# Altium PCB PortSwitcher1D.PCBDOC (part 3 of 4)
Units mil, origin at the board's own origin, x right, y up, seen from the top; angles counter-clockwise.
Board outline 6005.03 x 6005.03 mil, 4 copper layers (Top Layer, InternalPlane1, InternalPlane2, Bottom Layer); 153 components, 325 nets, 1175 pads, 173 vias.
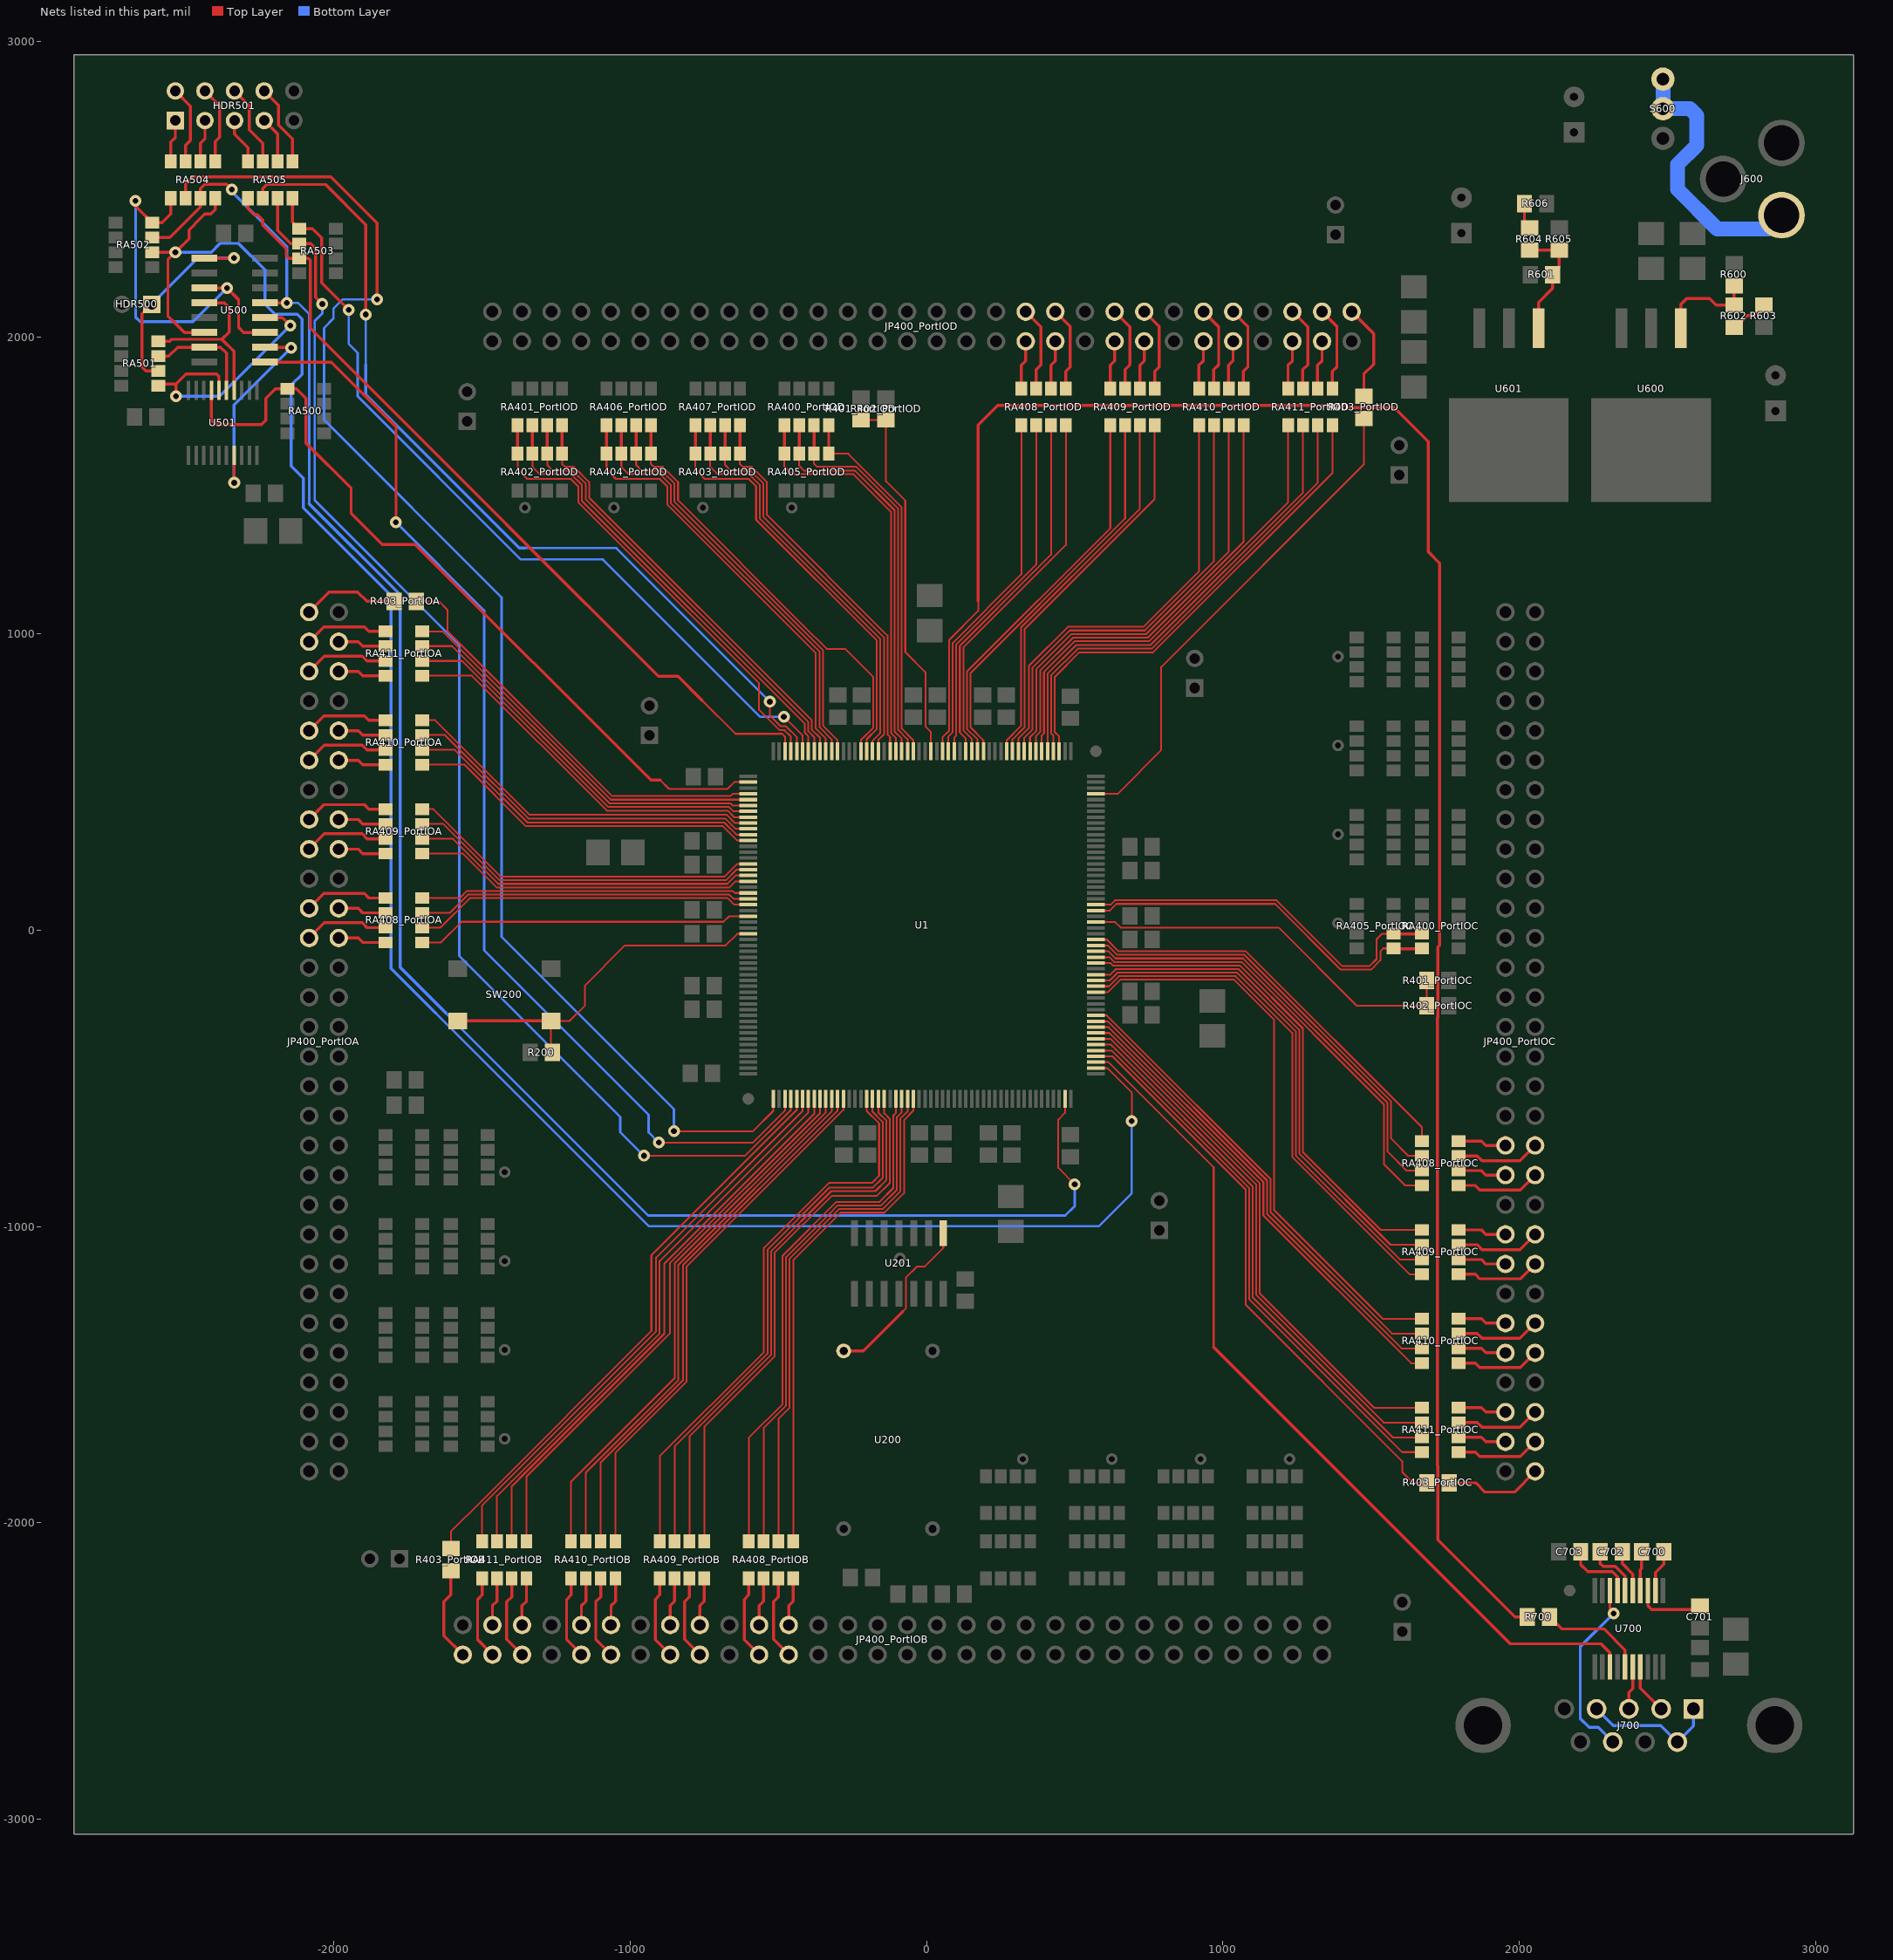
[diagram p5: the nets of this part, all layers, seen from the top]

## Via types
v1: diameter 40, hole 19.68, Top Layer to Bottom Layer, 173 vias

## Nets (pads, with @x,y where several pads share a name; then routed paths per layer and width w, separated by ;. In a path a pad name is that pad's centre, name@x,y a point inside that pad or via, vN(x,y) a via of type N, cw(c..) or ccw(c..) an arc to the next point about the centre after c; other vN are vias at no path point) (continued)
INC14: RA400_PortIOC.7 RA405_PortIOC.6 U1.30 | length 1281.8
  Top Layer w6: U1.30@571.35,86.19 621.14,86.19 635.71,100.77 1180.55,100.77 1401.82,-120.5 1495.13,-120.5 1518.2,-97.43 1518.2,-30.74 1537.53,-11.41 RA405_PortIOC.6@1575.24,-11.41
  Top Layer w10: RA405_PortIOC.6@1574.1,-12.55 RA400_PortIOC.7@1670.1,-12.55
INC15: RA400_PortIOC.8 RA405_PortIOC.5 U1.29 | length 1248.7
  Top Layer w6: U1.29@571.35,66.5 618.42,66.51 640.68,88.77 1175.58,88.77 1397.65,-133.3 1499.3,-133.3 1531,-101.61 1531,-71.09 1540.68,-61.41 RA405_PortIOC.5@1575.24,-61.41
  Top Layer w10: RA405_PortIOC.5@1574.1,-62.55 RA400_PortIOC.8@1670.1,-62.55
INC16: R401_PortIOC.2 R402_PortIOC.1 U1.27 | length 1582.4
  Top Layer w6: U1.27@571.35,27.13 636.49,27.14 654.86,8.77 1187.78,8.77 ; 1374.65,-178.1 1187.78,8.77 ; R401_PortIOC.2@1687.6,-170 R402_PortIOC.1@1687.6,-255 1451.54,-255 1187.78,8.77
IND0: RA401_PortIOD.5 RA402_PortIOD.8 U1.101 | length 1578.3
  Top Layer w6: RA402_PortIOD.8@-1380.26,1607.8 -1380.26,1554.93 -1348.53,1523.2 -1200.63,1523.2 -1175.49,1498.06 -1175.49,1444.01 -565.46,833.98 -565.46,743.67 -496.56,674.77 -479.83,674.77 -458.18,653.12 U1.101@-458.18,603.91
  Top Layer w10: RA402_PortIOD.8@-1380.26,1607.8 RA401_PortIOD.5@-1380.26,1703.8
IND1: RA401_PortIOD.6 RA402_PortIOD.7 U1.98 | length 1547.7
  Top Layer w6: RA402_PortIOD.7@-1330.26,1607.8 -1330.26,1563.99 -1305.04,1538.76 -1199.21,1538.76 -1163.49,1503.04 -1163.49,1448.98 -411.11,696.6 -411.11,666.32 ; -411.11,666.42 -399.12,654.43 U1.98@-399.12,603.91
  Top Layer w10: RA402_PortIOD.7@-1330.26,1607.8 RA401_PortIOD.6@-1330.26,1703.8
IND2: RA401_PortIOD.7 RA402_PortIOD.6 U1.97 | length 1512.1
  Top Layer w6: RA402_PortIOD.6@-1280.26,1607.8 -1280.26,1570.09 -1260.93,1550.76 -1194.24,1550.76 -1150.89,1507.4 -1150.89,1454.09 -399.11,702.32 -399.11,671.42 -379.44,651.75 U1.97@-379.44,603.91
  Top Layer w10: RA402_PortIOD.6@-1280.26,1607.8 RA401_PortIOD.7@-1280.26,1703.8
IND3: RA401_PortIOD.8 RA402_PortIOD.5 U1.96 | length 1478.4
  Top Layer w6: RA402_PortIOD.5@-1230.26,1607.8 -1230.26,1573.24 -1220.58,1563.55 -1190.07,1563.55 -1138.89,1512.37 -1138.89,1459.81 -387.11,708.03 -387.11,676.39 -359.75,649.03 U1.96@-359.75,603.91
  Top Layer w10: RA402_PortIOD.5@-1230.26,1607.8 RA401_PortIOD.8@-1230.26,1703.8
IND4: RA404_PortIOD.8 RA406_PortIOD.5 U1.95 | length 1493.1
  Top Layer w6: RA404_PortIOD.8@-1080.26,1607.8 -1080.26,1554.93 -1048.53,1523.2 -900.63,1523.2 -875.49,1498.06 -875.49,1436.84 -375.11,936.46 -375.11,681.42 -340.07,646.38 U1.95@-340.07,603.91
  Top Layer w10: RA404_PortIOD.8@-1080.26,1607.8 RA406_PortIOD.5@-1080.26,1703.8
IND5: RA404_PortIOD.7 RA406_PortIOD.6 U1.94 | length 1455.9
  Top Layer w6: RA404_PortIOD.7@-1030.26,1607.8 -1030.26,1563.99 -1005.04,1538.76 -899.21,1538.76 -863.49,1503.04 -863.49,1441.82 -361.11,939.43 -361.11,684.42 -320.38,643.69 U1.94@-320.38,603.91
  Top Layer w10: RA404_PortIOD.7@-1030.26,1607.8 RA406_PortIOD.6@-1030.26,1703.8
IND6: RA404_PortIOD.6 RA406_PortIOD.7 U1.93 | length 1420.4
  Top Layer w6: RA404_PortIOD.6@-980.26,1607.8 -980.26,1570.09 -960.93,1550.76 -894.24,1550.76 -850.89,1507.4 -850.89,1446.18 -349.11,944.4 -349.11,689.42 -300.7,641.01 U1.93@-300.7,603.91
  Top Layer w10: RA404_PortIOD.6@-980.26,1607.8 RA406_PortIOD.7@-980.26,1703.8
IND7: RA404_PortIOD.5 RA406_PortIOD.8 U1.89 | length 1482.2
  Top Layer w6: RA404_PortIOD.5@-930.26,1607.8 -930.26,1573.24 -920.58,1563.55 -890.07,1563.55 -838.89,1512.37 -838.89,1451.15 -414.55,1026.82 -337.36,949.62 -275.31,949.62 -180.11,854.42 -180.11,683.4 -221.96,641.55 U1.89@-221.96,603.91
  Top Layer w10: RA404_PortIOD.5@-930.26,1607.8 RA406_PortIOD.8@-930.26,1703.8
IND8: RA403_PortIOD.8 RA407_PortIOD.5 U1.88 | length 1454.2
  Top Layer w6: RA403_PortIOD.8@-780.26,1607.8 -780.26,1554.93 -748.53,1523.2 -600.63,1523.2 -575.49,1498.06 -575.49,1384.61 -168.11,977.22 -168.11,678.43 -202.27,644.26 U1.88@-202.27,603.91
  Top Layer w10: RA403_PortIOD.8@-780.26,1607.8 RA407_PortIOD.5@-780.26,1703.8
IND9: RA403_PortIOD.7 RA407_PortIOD.6 U1.87 | length 1410.7
  Top Layer w6: RA403_PortIOD.7@-730.26,1607.8 -730.26,1563.99 -705.04,1538.76 -599.21,1538.76 -563.49,1503.04 -563.49,1390.09 -156.11,982.7 -156.11,665.51 -182.59,639.03 U1.87@-182.59,603.91
  Top Layer w10: RA403_PortIOD.7@-730.26,1607.8 RA407_PortIOD.6@-730.26,1703.8
IND10: RA403_PortIOD.6 RA407_PortIOD.7 U1.86 | length 1368.8
  Top Layer w6: RA403_PortIOD.6@-680.26,1607.8 -680.26,1570.09 -660.93,1550.76 -594.24,1550.76 -550.89,1507.4 -550.89,1394.45 -144.11,987.67 -144.11,660.54 -162.9,641.74 U1.86@-162.9,603.91
  Top Layer w10: RA403_PortIOD.6@-680.26,1607.8 RA407_PortIOD.7@-680.26,1703.8
IND11: RA403_PortIOD.5 RA407_PortIOD.8 U1.84 | length 1327.7
  Top Layer w6: RA403_PortIOD.5@-630.26,1607.8 -630.26,1573.24 -620.58,1563.55 -590.07,1563.55 -538.89,1512.37 -538.89,1401.15 -132.11,994.37 -132.11,660.54 -123.53,651.96 U1.84@-123.53,603.91
  Top Layer w10: RA403_PortIOD.5@-630.26,1607.8 RA407_PortIOD.8@-630.26,1703.8
IND12: RA400_PortIOD.5 RA405_PortIOD.8 U1.83 | length 1377.2
  Top Layer w6: RA405_PortIOD.8@-480.26,1607.8 -480.26,1564.97 -454.05,1538.76 -246.85,1538.76 -120.11,1412.01 -120.11,665.51 -103.85,649.25 U1.83@-103.85,603.91
  Top Layer w10: RA405_PortIOD.8@-480.26,1607.8 RA400_PortIOD.5@-480.26,1703.8
IND13: RA400_PortIOD.6 RA405_PortIOD.7 U1.82 | length 1344
  Top Layer w6: RA405_PortIOD.7@-430.26,1607.8 -430.26,1567.13 -413.89,1550.76 -241.88,1550.76 -108.11,1416.98 -108.11,670.48 -84.16,646.53 U1.82@-84.16,603.91
  Top Layer w10: RA405_PortIOD.7@-430.26,1607.8 RA400_PortIOD.6@-430.26,1703.8
IND14: RA400_PortIOD.7 RA405_PortIOD.6 U1.81 | length 1308
  Top Layer w6: RA405_PortIOD.6@-380.26,1607.8 -380.26,1574.22 -370.58,1564.54 -238.69,1564.54 -96.11,1421.95 -96.11,675.45 -64.48,643.82 U1.81@-64.48,603.91
  Top Layer w10: RA405_PortIOD.6@-380.26,1607.8 RA400_PortIOD.7@-380.26,1703.8
IND15: RA400_PortIOD.8 RA405_PortIOD.5 U1.80 | length 1256.6
  Top Layer w6: RA405_PortIOD.5@-330.26,1607.8 -264.64,1607.8 -84.11,1427.27 -84.11,680.42 -44.79,641.1 U1.80@-44.79,603.91
  Top Layer w10: RA405_PortIOD.5@-330.26,1607.8 RA400_PortIOD.8@-330.26,1703.8
IND16: R401_PortIOD.2 R402_PortIOD.1 U1.77 | length 1265.5
  Top Layer w6: R401_PortIOD.2@-222.07,1721.73 R402_PortIOD.1@-137.07,1721.73 -137.07,1514.67 -72.11,1449.71 -72.11,938.67 -4.11,870.67 -4.11,687.42 14.26,669.05 U1.77@14.26,603.91
JTAG_NEXUS_TCK: RA503.2 RA505.3 U1.160 | length 4401.5
  Top Layer w6: v1(-954,-761.05) -612.55,-761.05 -458.18,-606.68 U1.160@-458.18,-569.32
  Top Layer w10: RA505.3@-2190.26,2470.29 -2190.26,2361.54 -2146.02,2317.29 -2078.12,2317.29 -2061.98,2301.16 -2061.98,2135.84 v1(-2039.35,2113.21)
  Bottom Layer w8: v1(-2039.35,2113.21) -2039.35,2081.72 -2064.94,2056.14 -2064.94,1450.98 -1576.87,962.92 -1576.87,-87.01 -1033.7,-630.18 -1033.7,-681.35 v1(-954,-761.05)
JTAG_NEXUS_TDI: RA503.3 RA505.1 U1.102 | length 2793.5
  Top Layer w6: -757.2,774.97 -645,662.77 -568.25,662.77 -487.52,662.77 -477.86,653.12 U1.102@-477.86,603.91
  Top Layer w10: RA505.1@-2290.26,2470.29 -2290.26,2434.91 -2269.1,2413.75 -2257.3,2413.75 -2240.26,2396.72 -2240.26,2379.07 -2161.28,2300.08 -2161.28,2276.47 -2152.1,2267.29 -2086.18,2267.29 -2079.7,2260.81 -2079.7,2031.54 -1450.79,1402.63 -1385.85,1337.7 -904.8,856.64 -838.87,856.64 -757.2,774.97
JTAG_NEXUS_TDO: RA505.2 U1.100 | length 3023.3
  Top Layer w6: v1(-529.04,771.23) -529.04,724.97 -492.63,688.55 -474.91,688.55 -438.49,652.13 U1.100@-438.49,603.91
  Top Layer w10: RA505.2@-2240.26,2470.29 -2240.26,2503.18 -2226.79,2516.65 -2028.53,2516.65 -1892.74,2380.86 v1(-1892.74,2077.79)
  Bottom Layer w8: -1892.74,1907.56 v1(-1892.74,2077.79) ; -1355.47,1289.6 -1047.42,1289.6 v1(-529.04,771.23)
  Bottom Layer w10: -1892.74,1907.56 -1892.74,1808.17 -1374.17,1289.6 -1355.47,1289.6
JTAG_NEXUS_TMS: RA503.1 RA505.4 U1.99 | length 2814.2
  Top Layer w6: v1(-481.8,720.05) -419.77,658.02 -419.77,657.12 ; U1.99@-418.81,603.91 -418.81,657.12
  Top Layer w10: RA505.4@-2140.26,2470.29 -2140.26,2390.29 RA503.1@-2117.26,2367.29 -2072.03,2367.29 -2041.32,2336.58 -2041.32,2185.04 v1(-1949.81,2093.53)
  Bottom Layer w8: v1(-1949.81,2093.53) -1949.81,1978.4 -1919.98,1948.58 -1919.98,1801.96 -1369.25,1251.23 -1092.74,1251.23 -561.56,720.05 v1(-481.8,720.05)
NetC700_1: C700.1 U700.2 | length 142.6
  Top Layer w10: U700.2@2459.3,-2228.77 2459.3,-2167.38 2487.14,-2139.55 C700.1@2487.14,-2097.71
NetC700_2: C700.2 U700.4 | length 132.8
  Top Layer w10: U700.4@2408.12,-2228.77 2408.12,-2158.54 2412.33,-2154.33 C700.2@2412.33,-2097.71
NetC701_2: C701.2 U700.3 | length 236.7
  Top Layer w10: U700.3@2433.71,-2228.77 2433.71,-2279.16 2446.7,-2292.16 2597.89,-2292.16 C701.2@2609.74,-2280.31
NetC702_1: C702.1 U700.5 | length 145.7
  Top Layer w10: C702.1@2347.14,-2097.71 2347.14,-2137.49 2382.53,-2172.88 U700.5@2382.53,-2228.77
NetC702_2: C702.2 U700.6 | length 190.9
  Top Layer w10: C702.2@2272.33,-2097.71 2272.33,-2137.47 2282.38,-2147.51 2324.69,-2147.51 2356.94,-2179.76 U700.6@2356.94,-2228.77
NetC703_1: C703.1 U700.7 | length 230.9
  Top Layer w10: C703.1@2207.14,-2097.71 2207.14,-2141.15 2231.21,-2165.22 2313.86,-2165.22 2331.35,-2182.71 U700.7@2331.35,-2228.77
NetHDR500_1: HDR500.1 RA501.2 U500.1 | length 727.9
  Top Layer w10: HDR500.1@-2615.26,2112.29 -2647.46,2080.09 -2647.46,1900.67 -2634.09,1887.29 RA501.2@-2593.26,1887.29 ; U500.1@-2437.63,2267.29 -2338.9,2267.29 v1(-2337.5,2268.68)
  Bottom Layer w10: HDR500.1@-2615.26,2112.29 -2458.87,2268.68 v1(-2337.5,2268.68)
NetJ700_1: J700.1 J700.4 J700.6 | length 453.3
  Bottom Layer w10: J700.4@2260.68,-2627.79 2316.68,-2683.79 2477.51,-2683.79 J700.6@2533.32,-2739.6 2587.85,-2685.07 J700.1@2587.85,-2627.79
NetR600_1: R600.1 R602.2 U600.1 | length 342.3
  Top Layer w10: U600.1@2544.74,2032.29 2544.74,2111.86 2564.78,2131.91 2641.54,2131.91 2663.75,2109.69 R602.2@2724.74,2109.69 R600.1@2724.74,2174.89
NetR601_1: R601.1 R604.2 R605.2 U601.1 | length 391.6
  Top Layer w10: R604.2@2034.74,2294.89 R605.2@2134.74,2294.89 2134.74,2234.89 R601.1@2112.14,2212.29 2112.14,2166.34 2064.74,2118.94 U601.1@2064.74,2032.29
NetR602_1: R602.1 R603.2 | length 131
  Top Layer w10: R602.1@2724.74,2034.89 2729.51,2034.89 2769.46,2074.84 2789.88,2074.84 R603.2@2824.74,2109.69
NetR604_1: R604.1 R606.2 | length 89.8
  Top Layer w10: R606.2@2017.33,2452.29 2017.33,2387.1 R604.1@2034.74,2369.69
NetR700_1: R700.1 U700.15 | length 358.4
  Top Layer w10: R700.1@2102.14,-2317.71 2142.51,-2358.08 2285.83,-2358.08 2356.94,-2429.19 U700.15@2356.94,-2486.65
NetRA501_1: RA501.1 U500.12 U501.6 | length 893.6
  Top Layer w10: RA501.1@-2593.26,1837.29 -2587.76,1842.79 -2533.32,1842.79 ; v1(-2533.32,1802.27) -2533.32,1842.79 ; U501.6@-2388.06,1821.54 -2388.06,1868.57 -2396.54,1877.05 -2499.06,1877.05 -2533.32,1842.79 ; U500.12@-2232.9,2067.29 -2174.49,2067.29 v1(-2147.59,2040.4)
  Bottom Layer w10: v1(-2533.32,1802.27) -2385.72,1802.27 v1(-2147.59,2040.4)
NetRA501_3: RA501.3 U500.7 U501.5 | length 377.2
  Top Layer w10: RA501.3@-2593.26,1937.29 -2557.7,1937.29 -2527.7,1967.29 -2382.48,1967.29 -2362.47,1947.28 U501.5@-2362.47,1821.54
NetRA501_4: RA501.4 U500.4 U501.4 | length 615.7
  Top Layer w10: RA501.4@-2593.26,1987.29 -2553.98,1987.29 -2547.13,1994.15 -2377.85,1994.15 ; U500.4@-2437.63,2117.29 -2370.12,2117.29 -2353.25,2100.42 -2353.25,2018.75 -2377.85,1994.15 ; U501.4@-2336.88,1821.54 -2336.88,1953.18 -2377.85,1994.15
NetU200_8: U200.8 U201.1 | length 591.3
  Top Layer w6: -81.1,-1287.72 -70.38,-1277 -70.38,-1172.67 -32.98,-1135.27 -7,-1135.27 56,-1072.28 U201.1@56,-1022.08
  Top Layer w10: U200.8@-280,-1420 -213.38,-1420 -81.1,-1287.72
O0_PortIOA: JP400_PortIOA.38 RA408_PortIOA.4 | length 164.2
  Top Layer w10: JP400_PortIOA.38@-1983.77,-26.41 -1918.02,-26.41 -1903.02,-41.41 RA408_PortIOA.4@-1825.77,-41.41
O0_PortIOB: JP400_PortIOB.38 RA408_PortIOB.4 | length 164.2
  Top Layer w10: JP400_PortIOB.38@-465.26,-2344.91 -465.26,-2279.17 -450.26,-2264.17 RA408_PortIOB.4@-450.26,-2186.91
O0_PortIOC: JP400_PortIOC.38 RA408_PortIOC.4 | length 164.2
  Top Layer w10: RA408_PortIOC.4@1795.24,-711.41 1872.49,-711.41 1887.49,-726.41 JP400_PortIOC.38@1953.24,-726.41
O0_PortIOD: JP400_PortIOD.38 RA408_PortIOD.4 | length 164.2
  Top Layer w10: RA408_PortIOD.4@319.34,1829.37 319.34,1906.62 334.34,1921.62 JP400_PortIOD.38@334.34,1987.37
O1_PortIOA: JP400_PortIOA.37 RA408_PortIOA.3 | length 286.2
  Top Layer w10: JP400_PortIOA.37@-2083.77,-26.41 -2032.19,25.17 -1905.03,25.17 -1888.45,8.59 RA408_PortIOA.3@-1825.77,8.59
O1_PortIOB: JP400_PortIOB.37 RA408_PortIOB.3 | length 286.2
  Top Layer w10: RA408_PortIOB.3@-500.26,-2186.91 -500.26,-2249.6 -516.84,-2266.17 -516.84,-2393.34 JP400_PortIOB.37@-465.26,-2444.91
O1_PortIOC: JP400_PortIOC.37 RA408_PortIOC.3 | length 286.2
  Top Layer w10: RA408_PortIOC.3@1795.24,-761.41 1857.93,-761.41 1874.5,-777.98 2001.66,-777.98 JP400_PortIOC.37@2053.24,-726.41
O1_PortIOD: JP400_PortIOD.37 RA408_PortIOD.3 | length 286.2
  Top Layer w10: JP400_PortIOD.37@334.34,2087.37 385.92,2035.8 385.92,1908.63 369.34,1892.06 RA408_PortIOD.3@369.34,1829.37
O2_PortIOA: JP400_PortIOA.40 RA408_PortIOA.2 | length 164.2
  Top Layer w10: JP400_PortIOA.40@-1983.77,73.59 -1918.02,73.59 -1903.02,58.59 RA408_PortIOA.2@-1825.77,58.59
O2_PortIOB: JP400_PortIOB.40 RA408_PortIOB.2 | length 164.2
  Top Layer w10: JP400_PortIOB.40@-565.26,-2344.91 -565.26,-2279.17 -550.26,-2264.17 RA408_PortIOB.2@-550.26,-2186.91
O2_PortIOC: JP400_PortIOC.40 RA408_PortIOC.2 | length 164.2
  Top Layer w10: RA408_PortIOC.2@1795.24,-811.41 1872.49,-811.41 1887.49,-826.41 JP400_PortIOC.40@1953.24,-826.41
O2_PortIOD: JP400_PortIOD.40 RA408_PortIOD.2 | length 164.2
  Top Layer w10: RA408_PortIOD.2@419.34,1829.37 419.34,1906.62 434.34,1921.62 JP400_PortIOD.40@434.34,1987.37
O3_PortIOA: JP400_PortIOA.39 RA408_PortIOA.1 | length 284.9
  Top Layer w10: JP400_PortIOA.39@-2083.77,73.59 -2033.77,123.59 -1897.16,123.59 -1882.16,108.59 RA408_PortIOA.1@-1825.77,108.59
O3_PortIOB: JP400_PortIOB.39 RA408_PortIOB.1 | length 284.9
  Top Layer w10: RA408_PortIOB.1@-600.26,-2186.91 -600.26,-2243.3 -615.26,-2258.3 -615.26,-2394.91 JP400_PortIOB.39@-565.26,-2444.91
O3_PortIOC: JP400_PortIOC.39 RA408_PortIOC.1 | length 284.9
  Top Layer w10: RA408_PortIOC.1@1795.24,-861.41 1851.63,-861.41 1866.63,-876.41 2003.24,-876.41 JP400_PortIOC.39@2053.24,-826.41
O3_PortIOD: JP400_PortIOD.39 RA408_PortIOD.1 | length 284.9
  Top Layer w10: JP400_PortIOD.39@434.34,2087.37 484.34,2037.37 484.34,1900.76 469.34,1885.76 RA408_PortIOD.1@469.34,1829.37
O4_PortIOA: JP400_PortIOA.44 RA409_PortIOA.4 | length 164.2
  Top Layer w10: JP400_PortIOA.44@-1983.77,273.59 -1918.02,273.59 -1903.02,258.59 RA409_PortIOA.4@-1825.77,258.59
O4_PortIOB: JP400_PortIOB.44 RA409_PortIOB.4 | length 164.2
  Top Layer w10: JP400_PortIOB.44@-765.26,-2344.91 -765.26,-2279.17 -750.26,-2264.17 RA409_PortIOB.4@-750.26,-2186.91
O4_PortIOC: JP400_PortIOC.44 RA409_PortIOC.4 | length 164.2
  Top Layer w10: RA409_PortIOC.4@1795.24,-1011.41 1872.49,-1011.41 1887.49,-1026.41 JP400_PortIOC.44@1953.24,-1026.41
O4_PortIOD: JP400_PortIOD.44 RA409_PortIOD.4 | length 164.2
  Top Layer w10: RA409_PortIOD.4@619.34,1829.37 619.34,1906.62 634.34,1921.62 JP400_PortIOD.44@634.34,1987.37
O5_PortIOA: JP400_PortIOA.43 RA409_PortIOA.3 | length 286.2
  Top Layer w10: JP400_PortIOA.43@-2083.77,273.59 -2032.19,325.17 -1905.03,325.17 -1888.45,308.59 RA409_PortIOA.3@-1825.77,308.59
O5_PortIOB: JP400_PortIOB.43 RA409_PortIOB.3 | length 286.2
  Top Layer w10: RA409_PortIOB.3@-800.26,-2186.91 -800.26,-2249.6 -816.84,-2266.17 -816.84,-2393.34 JP400_PortIOB.43@-765.26,-2444.91
O5_PortIOC: JP400_PortIOC.43 RA409_PortIOC.3 | length 286.2
  Top Layer w10: RA409_PortIOC.3@1795.24,-1061.41 1857.93,-1061.41 1874.5,-1077.98 2001.66,-1077.98 JP400_PortIOC.43@2053.24,-1026.41
O5_PortIOD: JP400_PortIOD.43 RA409_PortIOD.3 | length 286.2
  Top Layer w10: JP400_PortIOD.43@634.34,2087.37 685.92,2035.8 685.92,1908.63 669.34,1892.06 RA409_PortIOD.3@669.34,1829.37
O6_PortIOA: JP400_PortIOA.46 RA409_PortIOA.2 | length 164.2
  Top Layer w10: JP400_PortIOA.46@-1983.77,373.59 -1918.02,373.59 -1903.02,358.59 RA409_PortIOA.2@-1825.77,358.59
O6_PortIOB: JP400_PortIOB.46 RA409_PortIOB.2 | length 164.2
  Top Layer w10: JP400_PortIOB.46@-865.26,-2344.91 -865.26,-2279.17 -850.26,-2264.17 RA409_PortIOB.2@-850.26,-2186.91
O6_PortIOC: JP400_PortIOC.46 RA409_PortIOC.2 | length 164.2
  Top Layer w10: RA409_PortIOC.2@1795.24,-1111.41 1872.49,-1111.41 1887.49,-1126.41 JP400_PortIOC.46@1953.24,-1126.41
O6_PortIOD: JP400_PortIOD.46 RA409_PortIOD.2 | length 164.2
  Top Layer w10: RA409_PortIOD.2@719.34,1829.37 719.34,1906.62 734.34,1921.62 JP400_PortIOD.46@734.34,1987.37
O7_PortIOA: JP400_PortIOA.45 RA409_PortIOA.1 | length 284.9
  Top Layer w10: JP400_PortIOA.45@-2083.77,373.59 -2033.77,423.59 -1897.16,423.59 -1882.16,408.59 RA409_PortIOA.1@-1825.77,408.59
O7_PortIOB: JP400_PortIOB.45 RA409_PortIOB.1 | length 284.9
  Top Layer w10: RA409_PortIOB.1@-900.26,-2186.91 -900.26,-2243.3 -915.26,-2258.3 -915.26,-2394.91 JP400_PortIOB.45@-865.26,-2444.91
O7_PortIOC: JP400_PortIOC.45 RA409_PortIOC.1 | length 284.9
  Top Layer w10: RA409_PortIOC.1@1795.24,-1161.41 1851.63,-1161.41 1866.63,-1176.41 2003.24,-1176.41 JP400_PortIOC.45@2053.24,-1126.41
O7_PortIOD: JP400_PortIOD.45 RA409_PortIOD.1 | length 284.9
  Top Layer w10: JP400_PortIOD.45@734.34,2087.37 784.34,2037.37 784.34,1900.76 769.34,1885.76 RA409_PortIOD.1@769.34,1829.37
O8_PortIOA: JP400_PortIOA.50 RA410_PortIOA.4 | length 164.2
  Top Layer w10: JP400_PortIOA.50@-1983.77,573.2 -1918.02,573.2 -1903.02,558.2 RA410_PortIOA.4@-1825.77,558.2
O8_PortIOB: JP400_PortIOB.50 RA410_PortIOB.4 | length 164.2
  Top Layer w10: JP400_PortIOB.50@-1064.87,-2344.91 -1064.87,-2279.16 -1049.87,-2264.16 RA410_PortIOB.4@-1049.87,-2186.91
O8_PortIOC: JP400_PortIOC.50 RA410_PortIOC.4 | length 164.2
  Top Layer w10: RA410_PortIOC.4@1795.24,-1311.02 1872.49,-1311.02 1887.49,-1326.02 JP400_PortIOC.50@1953.24,-1326.02
O8_PortIOD: JP400_PortIOD.50 RA410_PortIOD.4 | length 164.2
  Top Layer w10: RA410_PortIOD.4@918.95,1829.37 918.95,1906.62 933.95,1921.62 JP400_PortIOD.50@933.95,1987.37
O9_PortIOA: JP400_PortIOA.49 RA410_PortIOA.3 | length 286.2
  Top Layer w10: JP400_PortIOA.49@-2083.77,573.2 -2032.19,624.77 -1905.03,624.77 -1888.45,608.2 RA410_PortIOA.3@-1825.77,608.2
O9_PortIOB: JP400_PortIOB.49 RA410_PortIOB.3 | length 286.2
  Top Layer w10: RA410_PortIOB.3@-1099.87,-2186.91 -1099.87,-2249.6 -1116.45,-2266.17 -1116.45,-2393.34 JP400_PortIOB.49@-1064.87,-2444.91
O9_PortIOC: JP400_PortIOC.49 RA410_PortIOC.3 | length 286.2
  Top Layer w10: RA410_PortIOC.3@1795.24,-1361.02 1857.92,-1361.02 ; 1857.92,-1361.02 1874.5,-1377.59 2001.66,-1377.59 JP400_PortIOC.49@2053.24,-1326.02
O9_PortIOD: JP400_PortIOD.49 RA410_PortIOD.3 | length 286.2
  Top Layer w10: JP400_PortIOD.49@933.95,2087.37 985.52,2035.8 985.52,1908.63 968.95,1892.06 RA410_PortIOD.3@968.95,1829.37
O10_PortIOA: JP400_PortIOA.52 RA410_PortIOA.2 | length 164.2
  Top Layer w10: JP400_PortIOA.52@-1983.77,673.2 -1918.02,673.2 -1903.02,658.2 RA410_PortIOA.2@-1825.77,658.2
O10_PortIOB: JP400_PortIOB.52 RA410_PortIOB.2 | length 164.2
  Top Layer w10: JP400_PortIOB.52@-1164.87,-2344.91 -1164.87,-2279.16 -1149.87,-2264.16 RA410_PortIOB.2@-1149.87,-2186.91
O10_PortIOC: JP400_PortIOC.52 RA410_PortIOC.2 | length 164.2
  Top Layer w10: RA410_PortIOC.2@1795.24,-1411.02 1872.49,-1411.02 1887.49,-1426.02 JP400_PortIOC.52@1953.24,-1426.02
O10_PortIOD: JP400_PortIOD.52 RA410_PortIOD.2 | length 164.2
  Top Layer w10: RA410_PortIOD.2@1018.95,1829.37 1018.95,1906.62 1033.95,1921.62 JP400_PortIOD.52@1033.95,1987.37
O11_PortIOA: JP400_PortIOA.51 RA410_PortIOA.1 | length 284.9
  Top Layer w10: JP400_PortIOA.51@-2083.77,673.2 -2033.77,723.2 -1897.15,723.2 -1882.16,708.2 RA410_PortIOA.1@-1825.77,708.2
O11_PortIOB: JP400_PortIOB.51 RA410_PortIOB.1 | length 284.9
  Top Layer w10: RA410_PortIOB.1@-1199.87,-2186.91 -1199.87,-2243.3 -1214.87,-2258.3 -1214.87,-2394.91 JP400_PortIOB.51@-1164.87,-2444.91
O11_PortIOC: JP400_PortIOC.51 RA410_PortIOC.1 | length 284.9
  Top Layer w10: RA410_PortIOC.1@1795.24,-1461.02 1851.63,-1461.02 1866.62,-1476.01 2003.24,-1476.01 JP400_PortIOC.51@2053.24,-1426.02
O11_PortIOD: JP400_PortIOD.51 RA410_PortIOD.1 | length 284.9
  Top Layer w10: JP400_PortIOD.51@1033.95,2087.37 1083.95,2037.37 1083.95,1900.76 1068.95,1885.76 RA410_PortIOD.1@1068.95,1829.37
O12_PortIOA: JP400_PortIOA.56 RA411_PortIOA.4 | length 164.2
  Top Layer w10: JP400_PortIOA.56@-1983.77,873.59 -1918.02,873.59 -1903.02,858.59 RA411_PortIOA.4@-1825.77,858.59
O12_PortIOB: JP400_PortIOB.56 RA411_PortIOB.4 | length 164.2
  Top Layer w10: JP400_PortIOB.56@-1365.26,-2344.91 -1365.26,-2279.17 -1350.26,-2264.17 RA411_PortIOB.4@-1350.26,-2186.91
O12_PortIOC: JP400_PortIOC.56 RA411_PortIOC.4 | length 164.2
  Top Layer w10: RA411_PortIOC.4@1795.24,-1611.41 1872.49,-1611.41 1887.49,-1626.41 JP400_PortIOC.56@1953.24,-1626.41
O12_PortIOD: JP400_PortIOD.56 RA411_PortIOD.4 | length 164.2
  Top Layer w10: RA411_PortIOD.4@1219.34,1829.37 1219.34,1906.62 1234.34,1921.62 JP400_PortIOD.56@1234.34,1987.37
O13_PortIOA: JP400_PortIOA.55 RA411_PortIOA.3 | length 286.2
  Top Layer w10: JP400_PortIOA.55@-2083.77,873.59 -2032.19,925.17 -1905.03,925.17 -1888.45,908.59 RA411_PortIOA.3@-1825.77,908.59
O13_PortIOB: JP400_PortIOB.55 RA411_PortIOB.3 | length 286.2
  Top Layer w10: RA411_PortIOB.3@-1400.26,-2186.91 -1400.26,-2249.6 -1416.84,-2266.17 -1416.84,-2393.34 JP400_PortIOB.55@-1365.26,-2444.91
O13_PortIOC: JP400_PortIOC.55 RA411_PortIOC.3 | length 286.2
  Top Layer w10: RA411_PortIOC.3@1795.24,-1661.41 1857.93,-1661.41 1874.5,-1677.98 2001.66,-1677.98 JP400_PortIOC.55@2053.24,-1626.41
O13_PortIOD: JP400_PortIOD.55 RA411_PortIOD.3 | length 286.2
  Top Layer w10: JP400_PortIOD.55@1234.34,2087.37 1285.92,2035.8 1285.92,1908.63 1269.34,1892.06 RA411_PortIOD.3@1269.34,1829.37
O14_PortIOA: JP400_PortIOA.58 RA411_PortIOA.2 | length 164.2
  Top Layer w10: JP400_PortIOA.58@-1983.77,973.59 -1918.02,973.59 -1903.02,958.59 RA411_PortIOA.2@-1825.77,958.59
O14_PortIOB: JP400_PortIOB.58 RA411_PortIOB.2 | length 164.2
  Top Layer w10: JP400_PortIOB.58@-1465.26,-2344.91 -1465.26,-2279.17 -1450.26,-2264.17 RA411_PortIOB.2@-1450.26,-2186.91
O14_PortIOC: JP400_PortIOC.58 RA411_PortIOC.2 | length 164.2
  Top Layer w10: RA411_PortIOC.2@1795.24,-1711.41 1872.49,-1711.41 1887.49,-1726.41 JP400_PortIOC.58@1953.24,-1726.41
O14_PortIOD: JP400_PortIOD.58 RA411_PortIOD.2 | length 164.2
  Top Layer w10: RA411_PortIOD.2@1319.34,1829.37 1319.34,1906.62 1334.34,1921.62 JP400_PortIOD.58@1334.34,1987.37
O15_PortIOA: JP400_PortIOA.57 RA411_PortIOA.1 | length 284.9
  Top Layer w10: JP400_PortIOA.57@-2083.77,973.59 -2033.77,1023.59 -1897.16,1023.59 -1882.16,1008.59 RA411_PortIOA.1@-1825.77,1008.59
O15_PortIOB: JP400_PortIOB.57 RA411_PortIOB.1 | length 284.9
  Top Layer w10: RA411_PortIOB.1@-1500.26,-2186.91 -1500.26,-2243.3 -1515.26,-2258.3 -1515.26,-2394.91 JP400_PortIOB.57@-1465.26,-2444.91
O15_PortIOC: JP400_PortIOC.57 RA411_PortIOC.1 | length 284.9
  Top Layer w10: RA411_PortIOC.1@1795.24,-1761.41 1851.63,-1761.41 1866.63,-1776.41 2003.24,-1776.41 JP400_PortIOC.57@2053.24,-1726.41
O15_PortIOD: JP400_PortIOD.57 RA411_PortIOD.1 | length 284.9
  Top Layer w10: JP400_PortIOD.57@1334.34,2087.37 1384.34,2037.37 1384.34,1900.76 1369.34,1885.76 RA411_PortIOD.1@1369.34,1829.37
O16_PortIOA: JP400_PortIOA.59 R403_PortIOA.2 | length 328.1
  Top Layer w10: JP400_PortIOA.59@-2083.77,1073.59 -2015.92,1141.44 -1920.77,1141.44 -1889.01,1109.68 R403_PortIOA.2@-1796.95,1109.68
O16_PortIOB: JP400_PortIOB.59 R403_PortIOB.2 | length 319.6
  Top Layer w10: R403_PortIOB.2@-1605.5,-2161.9 -1605.5,-2242.15 -1629.5,-2266.15 -1629.5,-2380.67 JP400_PortIOB.59@-1565.26,-2444.91
O16_PortIOC: JP400_PortIOC.59 R403_PortIOC.2 | length 332.2
  Top Layer w10: R403_PortIOC.2@1762.83,-1865 1853.19,-1865 1884.36,-1896.17 1983.48,-1896.17 JP400_PortIOC.59@2053.24,-1826.41
O16_PortIOD: JP400_PortIOD.59 R403_PortIOD.2 | length 329.8
  Top Layer w10: JP400_PortIOD.59@1434.34,2087.37 1508.47,2013.24 1508.47,1909.94 1475.5,1876.97 R403_PortIOD.2@1475.5,1801.9
OUTA0: RA408_PortIOA.5 U1.129 | length 1136.4
  Top Layer w6: RA408_PortIOA.5@-1701.77,-41.41 -1639.34,-41.41 -1569.48,28.45 -685.39,28.45 -667.02,46.82 U1.129@-601.88,46.82
OUTA1: RA408_PortIOA.6 U1.127 | length 1150.5
  Top Layer w6: RA408_PortIOA.6@-1701.77,8.59 -1641.44,8.59 -1541.59,108.45 -671.21,108.45 -648.95,86.19 U1.127@-601.88,86.19
OUTA2: RA408_PortIOA.7 U1.126 | length 1131.5
  Top Layer w6: RA408_PortIOA.7@-1701.77,58.59 -1608.41,58.59 -1546.56,120.45 -666.24,120.45 -651.66,105.88 U1.126@-601.88,105.87
OUTA3: RA408_PortIOA.8 U1.125 | length 1112.6
  Top Layer w6: RA408_PortIOA.8@-1701.77,108.59 -1575.38,108.59 -1551.53,132.45 -654.39,132.45 -647.5,125.56 U1.125@-601.88,125.56
OUTA4: RA409_PortIOA.5 U1.123 | length 1155.7
  Top Layer w6: RA409_PortIOA.5@-1701.77,258.59 -1565.03,258.59 -1450.89,144.45 -665.39,144.45 -644.91,164.93 U1.123@-601.88,164.93
OUTA5: RA409_PortIOA.6 U1.122 | length 1174.6
  Top Layer w6: RA409_PortIOA.6@-1701.77,308.59 -1598.06,308.59 -1548.06,258.59 -1445.92,156.45 -672.52,156.45 -644.35,184.61 U1.122@-601.88,184.61
OUTA6: RA409_PortIOA.7 U1.121 | length 1193.5
  Top Layer w6: RA409_PortIOA.7@-1701.77,358.59 -1631.09,358.59 -1581.09,308.59 -1440.94,168.45 -677.52,168.45 -641.67,204.3 U1.121@-601.88,204.3
OUTA7: RA409_PortIOA.8 U1.120 | length 1212.4
  Top Layer w6: RA409_PortIOA.8@-1701.77,408.59 -1664.12,408.59 -1614.12,358.59 -1435.97,180.45 -682.52,180.45 -638.98,223.98 U1.120@-601.88,223.98
OUTA8: RA410_PortIOA.5 U1.116 | length 1205.9
  Top Layer w6: RA410_PortIOA.5@-1701.77,558.59 -1559.5,558.59 -1352.04,351.13 -687.39,351.13 -638.98,302.73 U1.116@-601.88,302.73
OUTA9: RA410_PortIOA.6 U1.115 | length 1218.4
  Top Layer w6: RA410_PortIOA.6@-1701.77,608.59 -1592.53,608.59 -1542.53,558.59 -1347.07,363.13 -682.39,363.13 -641.67,322.41 U1.115@-601.88,322.41
OUTA10: RA410_PortIOA.7 U1.114 | length 1231
  Top Layer w6: RA410_PortIOA.7@-1701.77,658.59 -1625.56,658.59 -1575.56,608.59 -1344.1,377.13 -679.39,377.13 -644.35,342.1 U1.114@-601.88,342.1
OUTA11: RA410_PortIOA.8 U1.113 | length 1243.5
  Top Layer w6: RA410_PortIOA.8@-1701.77,708.59 -1658.59,708.59 -1608.59,658.59 -1339.13,389.13 -674.39,389.13 -647.04,361.78 U1.113@-601.88,361.78
OUTA12: RA411_PortIOA.5 U1.112 | length 1297.5
  Top Layer w6: RA411_PortIOA.5@-1701.77,858.59 -1534.78,858.59 -1079.32,403.13 -671.39,403.13 -649.72,381.47 U1.112@-601.88,381.47
OUTA13: RA411_PortIOA.6 U1.111 | length 1310.1
  Top Layer w6: RA411_PortIOA.6@-1701.77,908.59 -1567.81,908.59 -1075.74,416.52 -667.78,416.52 -652.41,401.15 U1.111@-601.88,401.15
OUTA14: RA411_PortIOA.7 U1.110 | length 1322.6
  Top Layer w6: RA411_PortIOA.7@-1701.77,958.59 -1600.84,958.59 -1070.77,428.52 -662.78,428.52 -655.09,420.84 U1.110@-601.88,420.84
OUTA15: RA411_PortIOA.8 U1.109 | length 1335.2
  Top Layer w6: RA411_PortIOA.8@-1701.77,1008.59 -1633.87,1008.59 -1065.8,440.52 U1.109@-601.88,440.52
OUTA16: R403_PortIOA.1 U1.108 | length 1437.9
  Top Layer w6: R403_PortIOA.1@-1722.15,1109.68 -1645.96,1109.68 -1616.9,1080.62 -1616.9,1008.59 -1060.83,452.52 -662.06,452.52 -654.38,460.21 U1.108@-601.88,460.21
OUTB0: RA408_PortIOB.5 U1.181 | length 1748.2
  Top Layer w6: RA408_PortIOB.5@-450.26,-2062.91 -450.26,-1113.31 -303.65,-966.69 -290.33,-953.37 -142.42,-953.37 -76.42,-887.37 -76.42,-640.86 -44.79,-609.23 U1.181@-44.79,-569.32
OUTB1: RA408_PortIOB.6 U1.180 | length 1760.3
  Top Layer w6: RA408_PortIOB.6@-500.26,-2062.91 -500.26,-1649.8 -462.26,-1611.8 -462.26,-1108.34 -316.26,-962.33 -295.3,-941.37 -148.14,-941.37 -88.42,-881.65 -88.42,-635.89 -64.48,-611.95 U1.180@-64.48,-569.32
OUTB2: RA408_PortIOB.7 U1.179 | length 1772.4
  Top Layer w6: RA408_PortIOB.7@-550.26,-2062.91 -550.26,-1680.35 -474.26,-1604.35 -474.26,-1103.36 -328.26,-957.36 -299.66,-928.76 -153.25,-928.76 -100.42,-875.94 -100.42,-630.92 -84.16,-614.66 U1.179@-84.16,-569.32
OUTB3: RA408_PortIOB.8 U1.178 | length 1784.5
  Top Layer w6: RA408_PortIOB.8@-600.26,-2062.91 -600.26,-1713.38 -486.26,-1599.38 -486.26,-1098.39 -304.63,-916.76 -158.97,-916.76 -112.42,-870.22 -112.42,-857.42 -112.42,-625.95 -103.85,-617.38 U1.178@-103.85,-569.32
OUTB4: RA409_PortIOB.5 U1.176 | length 1849.7
  Top Layer w6: RA409_PortIOB.5@-750.26,-2062.91 -750.26,-1675.86 -513.11,-1438.7 -513.11,-1089.29 -319.91,-896.09 -167.82,-896.09 -124.42,-852.69 -124.42,-636.92 -143.22,-618.13 U1.176@-143.22,-569.32
OUTB5: RA409_PortIOB.6 U1.175 | length 1866.6
  Top Layer w6: RA409_PortIOB.6@-800.26,-2062.91 -800.26,-1708.89 -750.26,-1658.89 -525.11,-1433.73 -525.11,-1084.02 -321.62,-880.53 -172.93,-880.53 -136.42,-844.02 -136.42,-641.89 -162.9,-615.41 U1.175@-162.9,-569.32
OUTB6: RA409_PortIOB.7 U1.174 | length 1884.4
  Top Layer w6: RA409_PortIOB.7@-850.26,-2062.91 -850.26,-1741.92 -800.26,-1691.92 -537.11,-1428.76 -537.11,-1078.31 -327.33,-868.53 -180.62,-868.53 -148.42,-836.34 -148.42,-646.86 -182.59,-612.7 U1.174@-182.59,-569.32
OUTB7: RA409_PortIOB.8 U1.173 | length 1902.2
  Top Layer w6: RA409_PortIOB.8@-900.26,-2062.91 -900.26,-1774.95 -559.37,-1434.05 -549.11,-1423.79 -549.11,-1072.6 -329.3,-852.79 -184.56,-852.79 -160.42,-828.65 -160.42,-651.83 -202.27,-609.98 U1.173@-202.27,-569.32
OUTB8: RA410_PortIOB.5 U1.169 | length 1812.2
  Top Layer w6: RA410_PortIOB.5@-1050.26,-2062.91 -1050.26,-1764.25 -810.35,-1524.33 -810.35,-1135.76 -281.01,-606.43 U1.169@-281.01,-569.32
OUTB9: RA410_PortIOB.6 U1.168 | length 1824.8
  Top Layer w6: RA410_PortIOB.6@-1100.26,-2062.91 -1100.26,-1797.28 -822.35,-1519.36 -822.35,-1130.76 -300.7,-609.11 U1.168@-300.7,-569.32
OUTB10: RA410_PortIOB.7 U1.167 | length 1837.3
  Top Layer w6: RA410_PortIOB.7@-1150.26,-2062.91 -1150.26,-1830.31 -1100.26,-1780.31 -837.91,-1517.95 -837.91,-1129.32 -320.38,-611.8 U1.167@-320.38,-569.32
OUTB11: RA410_PortIOB.8 U1.166 | length 1849.9
  Top Layer w6: RA410_PortIOB.8@-1200.26,-2062.91 -1200.26,-1861.84 -1150.26,-1811.84 -849.91,-1511.49 -849.91,-1124.32 -340.07,-614.48 U1.166@-340.07,-569.32
OUTB12: RA411_PortIOB.5 U1.165 | length 1903.9
  Top Layer w6: RA411_PortIOB.5@-1350.26,-2062.91 -1350.26,-1843.78 -865.66,-1359.17 -865.66,-1123.07 -359.75,-617.17 U1.165@-359.75,-569.32
OUTB13: RA411_PortIOB.6 U1.164 | length 1916.4
  Top Layer w6: RA411_PortIOB.6@-1400.26,-2062.91 -1400.26,-1876.81 -1350.26,-1826.81 -885.34,-1361.88 -885.34,-1125.76 -379.44,-619.85 U1.164@-379.44,-569.32
OUTB14: RA411_PortIOB.7 U1.163 | length 1929
  Top Layer w6: RA411_PortIOB.7@-1450.26,-2062.91 -1450.26,-1909.83 -1400.26,-1859.83 -900.9,-1360.47 -900.9,-1116.38 -399.12,-614.6 U1.163@-399.12,-569.32
OUTB15: RA411_PortIOB.8 U1.162 | length 1941.5
  Top Layer w6: RA411_PortIOB.8@-1500.26,-2062.91 -1500.26,-1941.37 -1450.26,-1891.37 -912.9,-1354.01 -912.9,-1104.76 -418.81,-610.66 U1.162@-418.81,-569.32
OUTB16: R403_PortIOB.1 U1.161 | length 2001.2
  Top Layer w6: R403_PortIOB.1@-1605.5,-2087.1 -1605.5,-2029.64 -1500.26,-1924.4 -928.65,-1352.79 -928.65,-1096.88 -438.49,-606.72 U1.161@-438.49,-569.32
OUTC0: RA408_PortIOC.5 U1.24 | length 1408.4
  Top Layer w6: U1.24@571.35,-31.92 608.55,-31.92 647.86,-71.23 1077.2,-71.23 1671.24,-665.27 RA408_PortIOC.5@1671.24,-711.41
OUTC1: RA408_PortIOC.6 U1.23 | length 1467
  Top Layer w6: U1.23@571.35,-51.61 611.26,-51.6 642.89,-83.23 1072.23,-83.23 1567.22,-578.23 1567.22,-702.99 1625.64,-761.41 RA408_PortIOC.6@1671.24,-761.41
OUTC2: RA408_PortIOC.7 U1.22 | length 1502.5
  Top Layer w6: U1.22@571.35,-71.29 613.98,-71.29 637.92,-95.23 1067.26,-95.23 1555.22,-583.2 1555.22,-747.09 1619.54,-811.41 RA408_PortIOC.7@1671.24,-811.41
OUTC3: RA408_PortIOC.8 U1.21 | length 1537.4
  Top Layer w6: U1.21@571.35,-90.98 616.69,-90.97 632.95,-107.23 1062.29,-107.23 1543.22,-588.17 1543.22,-790.21 1614.42,-861.41 RA408_PortIOC.8@1671.24,-861.41
OUTC4: RA409_PortIOC.5 U1.20 | length 1717.3
  Top Layer w6: U1.20@571.35,-110.66 619.41,-110.66 627.98,-119.23 1057.32,-119.23 1269.56,-331.48 1269.56,-748.6 1532.38,-1011.41 RA409_PortIOC.5@1671.24,-1011.41
OUTC5: RA409_PortIOC.6 U1.18 | length 1737.3
  Top Layer w6: U1.18@571.35,-150.03 620.15,-150.03 638.95,-131.23 1052.35,-131.23 1257.56,-336.45 1257.56,-753.57 1565.4,-1061.41 RA409_PortIOC.6@1671.24,-1061.41
OUTC6: RA409_PortIOC.7 U1.17 | length 1757.1
  Top Layer w6: U1.17@571.35,-169.72 617.44,-169.71 643.92,-143.23 1047.37,-143.23 1050.71,-146.57 1245.56,-341.42 1245.56,-760.03 1596.94,-1111.41 RA409_PortIOC.7@1671.24,-1111.41
OUTC7: RA409_PortIOC.8 U1.16 | length 1776
  Top Layer w6: U1.16@571.35,-189.4 614.73,-189.4 648.89,-155.23 1042.41,-155.23 1233.56,-346.39 1233.56,-765 1629.97,-1161.41 RA409_PortIOC.8@1671.24,-1161.41
OUTC8: RA410_PortIOC.5 U1.15 | length 1967.7
  Top Layer w6: U1.15@571.35,-209.09 612.01,-209.08 653.86,-167.23 1037.44,-167.23 1172.73,-302.53 1172.73,-945.31 1538.83,-1311.41 RA410_PortIOC.5@1671.24,-1311.41
OUTC9: RA410_PortIOC.6 U1.11 | length 1610.1
  Top Layer w6: U1.11@571.35,-287.83 608.45,-287.83 656.86,-336.23 1160.73,-840.13 1160.73,-952.01 1570.13,-1361.41 RA410_PortIOC.6@1671.24,-1361.41
OUTC10: RA410_PortIOC.7 U1.10 | length 1623.1
  Top Layer w6: U1.10@571.35,-307.51 611.14,-307.51 651.86,-348.23 1148.73,-845.13 1148.73,-957.72 1602.41,-1411.41 RA410_PortIOC.7@1671.24,-1411.41
OUTC11: RA410_PortIOC.8 U1.9 | length 1636.1
  Top Layer w6: U1.9@571.35,-327.2 613.82,-327.2 1136.31,-849.68 1136.31,-963.02 1634.7,-1461.41 RA410_PortIOC.8@1671.24,-1461.41
OUTC12: RA411_PortIOC.5 U1.8 | length 1841.4
  Top Layer w6: U1.8@571.35,-346.88 616.51,-346.88 1124.31,-854.68 1124.31,-1226.38 1509.34,-1611.41 RA411_PortIOC.5@1671.24,-1611.41
OUTC13: RA411_PortIOC.6 U1.7 | length 1853.9
  Top Layer w6: U1.7@571.35,-366.57 619.19,-366.57 1112.31,-859.68 1112.31,-1231.35 1542.37,-1661.41 RA411_PortIOC.6@1671.24,-1661.41
OUTC14: RA411_PortIOC.7 U1.6 | length 1868.1
  Top Layer w6: U1.6@571.35,-386.25 621.88,-386.25 637.25,-401.62 ; 637.25,-401.65 1100.31,-864.71 1100.31,-1239.03 1572.69,-1711.41 RA411_PortIOC.7@1671.24,-1711.41
OUTC15: RA411_PortIOC.8 U1.5 | length 1881.1
  Top Layer w6: U1.5@571.35,-405.94 624.56,-405.94 1088.31,-869.68 1088.31,-1244.75 1604.97,-1761.41 RA411_PortIOC.8@1671.24,-1761.41
OUTC16: R403_PortIOC.1 U1.4 | length 1961.9
  Top Layer w6: U1.4@571.35,-425.62 627.28,-425.62 1076.31,-874.65 1076.31,-1263.27 1604.9,-1791.86 1604.9,-1828.27 1641.63,-1865 R403_PortIOC.1@1688.03,-1865
OUTD0: RA408_PortIOD.5 U1.74 | length 1202
  Top Layer w6: U1.74@73.32,603.91 73.32,653.69 87.89,668.27 87.89,969.35 319.74,1201.19 RA408_PortIOD.5@319.74,1703.8
OUTD1: RA408_PortIOD.6 U1.73 | length 1214.5
  Top Layer w6: U1.73@93,603.91 93,649.53 99.89,656.42 99.89,964.38 319.74,1184.22 369.74,1234.22 RA408_PortIOD.6@369.74,1703.8
OUTD2: RA408_PortIOD.7 U1.71 | length 1235.9
  Top Layer w6: U1.71@132.37,603.91 132.37,646.94 111.89,667.42 111.89,959.41 369.74,1217.25 419.74,1267.25 RA408_PortIOD.7@419.74,1703.8
OUTD3: RA408_PortIOD.8 U1.70 | length 1254.8
  Top Layer w6: U1.70@152.06,603.91 152.06,646.38 123.89,674.54 123.89,953.93 419.74,1249.77 469.74,1299.77 RA408_PortIOD.8@469.74,1703.8
OUTD4: RA409_PortIOD.5 U1.69 | length 1315.2
  Top Layer w6: U1.69@171.74,603.91 171.74,643.69 135.89,679.54 135.89,872.43 619.74,1356.27 RA409_PortIOD.5@619.74,1703.8
OUTD5: RA409_PortIOD.6 U1.68 | length 1334.1
  Top Layer w6: U1.68@191.43,603.91 191.43,641.01 147.89,684.54 147.89,867.46 619.74,1339.3 669.74,1389.3 RA409_PortIOD.6@669.74,1703.8
OUTD6: RA409_PortIOD.7 U1.64 | length 1286.1
  Top Layer w6: U1.64@270.17,603.91 270.17,641.01 318.58,689.42 318.58,1021.17 669.74,1372.33 719.74,1422.33 RA409_PortIOD.7@719.74,1703.8
OUTD7: RA409_PortIOD.8 U1.63 | length 1298.7
  Top Layer w6: U1.63@289.85,603.91 289.85,643.69 330.58,684.42 330.58,1016.2 719.74,1405.36 769.74,1455.36 RA409_PortIOD.8@769.74,1703.8
OUTD8: RA410_PortIOD.5 U1.62 | length 1501.9
  Top Layer w6: U1.62@309.54,603.91 309.54,646.38 344.58,681.42 344.58,891.68 476.47,1023.57 731.24,1023.57 919.74,1212.07 RA410_PortIOD.5@919.74,1703.8
OUTD9: RA410_PortIOD.6 U1.61 | length 1513.6
  Top Layer w6: U1.61@329.22,603.91 329.22,649.06 356.58,676.42 356.58,885.2 482.96,1011.57 736.21,1011.58 919.74,1195.1 969.74,1245.1 RA410_PortIOD.6@969.74,1703.8
OUTD10: RA410_PortIOD.7 U1.60 | length 1525.7
  Top Layer w6: U1.60@348.91,603.91 348.91,651.75 370.58,673.42 370.58,881.48 488.67,999.58 741.18,999.58 969.74,1228.13 1019.74,1278.13 RA410_PortIOD.7@1019.74,1703.8
OUTD11: RA410_PortIOD.8 U1.59 | length 1537.8
  Top Layer w6: U1.59@368.59,603.91 368.59,654.43 383.96,669.8 383.96,877.15 493.78,986.97 745.54,986.97 1069.74,1311.16 RA410_PortIOD.8@1069.74,1703.8
OUTD12: RA411_PortIOD.5 U1.58 | length 1591.3
  Top Layer w6: U1.58@388.28,603.91 388.28,657.12 395.96,664.8 395.96,871.43 499.5,974.97 750.51,974.97 1069.74,1294.19 1219.74,1444.19 RA411_PortIOD.5@1219.74,1703.8
OUTD13: RA411_PortIOD.6 U1.57 | length 1603.5
  Top Layer w6: U1.57@407.96,603.91 407.96,865.72 504.61,962.36 754.88,962.36 1269.74,1477.22 RA411_PortIOD.6@1269.74,1703.8
OUTD14: RA411_PortIOD.7 U1.56 | length 1621.9
  Top Layer w6: U1.56@427.65,603.91 427.65,656.4 419.96,664.09 419.96,860 510.33,950.36 759.85,950.36 1269.74,1460.25 1319.74,1510.25 RA411_PortIOD.7@1319.73,1703.8
OUTD15: RA411_PortIOD.8 U1.55 | length 1640.4
  Top Layer w6: U1.55@447.33,603.91 447.33,653.69 431.96,669.06 431.96,854.28 515.25,937.57 764.02,937.57 1369.74,1543.28 RA411_PortIOD.8@1369.74,1703.8
OUTD16: R403_PortIOD.1 U1.49 | length 1684.1
  Top Layer w6: U1.49@571.35,460.21 644.19,460.21 791.82,607.84 791.82,888.25 1475.5,1571.93 R403_PortIOD.1@1475.5,1727.1
PROGRAM: RA500.1 U1.106 U501.7 | length 2719
  Top Layer w6: -898.9,506.34 -869.08,476.52 -672,476.52 -648.95,499.58 U1.106@-601.88,499.58
  Top Layer w10: U501.7@-2413.65,1821.54 -2413.65,1720.97 -2398.51,1705.84 -2245.01,1705.84 -2230.25,1720.6 -2230.25,1794.4 -2197.35,1827.29 -2127.35,1827.29 -2094.46,1794.4 -2094.46,1643.84 -1941.94,1491.32 -1941.94,1406.7 -1837.15,1301.91 -1725.96,1301.91 -930.38,506.34 -898.9,506.34
PWR_IN: J600.1 S600.1 S600.2 | length 923.7
  Bottom Layer w50: S600.1@2484.74,2872.29 S600.2@2484.74,2772.29 2575.81,2772.29 2598.24,2749.86 2598.24,2648.51 2534.28,2584.55 2534.28,2499.92 2667.12,2367.08 2838.9,2367.08 J600.1@2884.74,2412.92
RS232_RX: R700.2 U1.75 | length 6883.3
  Top Layer w6: U1.75@53.63,603.91 53.63,650.98 75.89,673.24 75.89,979.2 174.17,1077.48 174.17,1110.94
  Top Layer w10: 174.17,1110.94 174.17,1705.27 240.1,1771.2 1415.98,1771.2 1422.86,1764.31 1577.35,1764.31 1692.48,1649.18 1692.48,1277.23 1730.86,1238.86 1730.86,-51.17 1724.95,-57.07 1724.95,-294.54 1723.97,-295.53 1723.97,-1806.14 1725.43,-1807.61 1725.43,-2057.72 1985.42,-2317.71 R700.2@2027.33,-2317.71
RS232_TX: U1.3 U700.13 | length 2963.7
  Top Layer w6: U1.3@571.35,-445.31 613.57,-445.31 968.54,-800.28 968.54,-1407.35
  Top Layer w10: 968.54,-1407.35 1969.46,-2408.27 2275.43,-2408.27 2305.76,-2438.6 U700.13@2305.76,-2486.65
RTS: J700.8 U700.8 | length 625.3
  Top Layer w10: U700.8@2305.76,-2228.77 2305.76,-2293.89 v1(2317.8,-2305.93)
  Bottom Layer w10: J700.8@2315.21,-2739.6 2266.29,-2690.68 2236.13,-2690.68 2205.62,-2660.17 2205.62,-2418.11 v1(2317.8,-2305.93)
RX: J700.3 U700.16 | length 146.4
  Top Layer w10: J700.3@2369.74,-2627.79 2369.74,-2571.83 2382.53,-2559.03 U700.16@2382.53,-2486.65
TCK: RA502.3 RA504.3 U1.207 U500.13 | length 6372.9
  Top Layer w6: U1.207@467.02,-569.32 467.02,-616.39 443.96,-639.45 443.96,-802.17 v1(499.5,-857.71)
  Top Layer w10: RA502.3@-2613.26,2337.29 -2554.26,2337.29 -2500.26,2391.28 -2450.26,2441.28 -2450.26,2503.19 -2436.38,2517.07 -2362.58,2517.07 v1(-2344.87,2499.36) ; U500.13@-2232.9,2117.29 v1(-2159.54,2117.29)
  Bottom Layer w8: v1(-2159.54,2117.29) -2121.17,2117.29 -2083.63,2079.76 -2083.63,1439.17 ; -1621.15,-280.86 -939.24,-962.77 467.88,-962.77 499.5,-931.15 v1(499.5,-857.71)
  Bottom Layer w10: v1(-2344.87,2499.36) -2344.87,2492.53 -2159.54,2307.2 v1(-2159.54,2117.29) ; -2083.63,1439.17 -1776.62,1132.16 -1776.62,-125.39 -1621.15,-280.86
TCK_HARD_A#: HDR501.3 RA504.6 | length 144.2
  Top Layer w10: RA504.6@-2450.26,2594.29 -2450.26,2655.8 -2435.26,2670.8 HDR501.3@-2435.26,2732.29
TCK_SOFT_A#: HDR501.7 RA505.6 | length 156.6
  Top Layer w10: HDR501.7@-2235.26,2732.29 -2190.26,2687.29 RA505.6@-2190.26,2594.29
TDI: U1.159 U500.9 | length 3826.3
  Top Layer w6: v1(-903.82,-716.77) -585.98,-716.77 -477.86,-608.65 U1.159@-477.86,-569.32
  Top Layer w10: U500.9@-2232.9,1917.29 -2008.74,1917.29 -1790.4,1698.95 -1790.4,1377.18 v1(-1790.84,1376.74)
  Bottom Layer w8: v1@-1790.89,1376.69 -1493.23,1079.03 -1493.23,-68.32 -938.26,-623.29 -938.26,-682.33 v1(-903.82,-716.77)
TDI_HARD_A#: HDR501.1 RA504.8 | length 144.2
  Top Layer w10: RA504.8@-2550.26,2594.29 -2550.26,2660.1 -2535.26,2675.1 HDR501.1@-2535.26,2732.29
TDI_PP: RA502.4 RA504.1 U500.3 U500.11 | length 1302.8
  Top Layer w10: v1(-2670.1,2461.55) -2670.1,2444.12 RA502.4@-2613.26,2387.29 -2580.02,2387.29 -2550.26,2417.05 RA504.1@-2550.26,2470.29 ; U500.3@-2437.63,2167.29 v1(-2361.08,2167.29) -2321.76,2127.97 -2321.76,2034.49 -2304.56,2017.29 U500.11@-2232.9,2017.29
  Bottom Layer w10: v1(-2670.1,2461.55) -2669.11,2460.56 -2669.11,2068.93 -2653.37,2053.19 -2475.18,2053.19 v1(-2361.08,2167.29)
TDI_SOFT_A#: HDR501.5 RA505.8 | length 156.6
  Top Layer w10: HDR501.5@-2335.26,2732.29 -2335.26,2686.61 -2290.26,2641.61 RA505.8@-2290.26,2594.29
TDO: RA504.2 U1.157 | length 4868.8
  Top Layer w6: v1(-852.65,-678.4) -585.98,-678.4 -517.23,-609.64 U1.157@-517.23,-569.32
  Top Layer w10: RA504.2@-2500.26,2470.29 -2500.26,2519.12 -2477.15,2542.24 -2010.82,2542.24 -1854.36,2385.78 v1(-1854.36,2128.96)
  Bottom Layer w8: v1(-1854.36,2128.96) -1970.47,2128.96 -2001.96,2097.47 -2001.96,2064.01 -2033.45,2032.52 -2033.45,1722.56 -1434.19,1123.31 -1434.19,-22.07 -852.65,-603.61 v1(-852.65,-678.4)
TDO_CFG: U500.10 U501.17 | length 717.5
  Top Layer w10: v1(-2336.52,1510.02) U501.17@-2336.52,1602.68 ; U500.10@-2232.9,1967.29 -2146.32,1967.29 v1(-2144.64,1965.61)
  Bottom Layer w10: v1(-2336.52,1510.02) -2337.5,1511 -2337.5,1772.75 v1(-2144.64,1965.61)
TDO_HARD_A#: HDR501.2 RA504.7 | length 265.9
  Top Layer w10: HDR501.2@-2535.26,2832.29 -2484.12,2781.15 -2484.12,2665.24 -2500.26,2649.09 RA504.7@-2500.26,2594.29
TDO_SOFT_A#: HDR501.6 RA505.7 | length 277.4
  Top Layer w10: HDR501.6@-2335.26,2832.29 -2285.35,2782.38 -2285.35,2700.66 -2240.26,2655.57 RA505.7@-2240.26,2594.29
TEST_BUTTON: R200.1 SW200.1 SW200.2 U1.132 | length 1250.7
  Top Layer w6: R200.1@-1262.86,-412.71 -1267.39,-408.18 SW200.1@-1267.39,-306.29 -1204.77,-306.29 -1153.75,-255.28 -1153.75,-187.38 -1017.92,-51.55 -678.39,-51.55 -639.08,-12.24 U1.132@-601.88,-12.24
  Top Layer w10: SW200.2@-1582.74,-306.29 SW200.1@-1267.39,-306.29
TMS: RA502.2 RA504.4 U1.2 U500.6 | length 7060
  Top Layer w6: U1.2@571.35,-464.99 609.64,-464.99 692.23,-547.58 v1(692.23,-643.96)
  Top Layer w10: RA502.2@-2613.26,2287.29 v1(-2535.29,2287.29) ; U500.6@-2437.63,2017.29 -2504.31,2017.29 -2535.29,2048.27 -2560.37,2073.35 -2560.37,2262.21 v1(-2535.29,2287.29) ; RA504.4@-2400.26,2470.29 -2400.26,2432.16 -2415.72,2416.7 -2435.48,2416.7 -2450.26,2401.92 -2489.04,2363.15 -2489.04,2333.54 v1(-2535.29,2287.29)
  Bottom Layer w8: -1655.19,-281.26 -1188.19,-748.26 -937.27,-999.18 581.04,-999.18 692.23,-887.99 v1(692.23,-643.96)
  Bottom Layer w10: v1(-2535.29,2287.29) -2414.34,2287.29 -2383.75,2317.88 -2322.74,2317.88 -2233.2,2228.34 -2233.2,2113.21 -2198.76,2078.77 -2123.98,2078.77 -2108.23,2063.03 -2108.23,1876.07 -2144.64,1839.66 -2144.64,1566.11 -2103.31,1524.78 -2103.31,1425.4 -1807.13,1129.21 -1807.13,-129.32 -1655.19,-281.26
TMS_HARD_A#: HDR501.4 RA504.5 | length 264.5
  Top Layer w10: HDR501.4@-2435.26,2832.29 -2385.72,2782.75 -2385.72,2676.06 -2400.26,2661.52 RA504.5@-2400.26,2594.29
TMS_SOFT_A#: HDR501.8 RA505.5 | length 277.4
  Top Layer w10: HDR501.8@-2235.26,2832.29 -2186.95,2783.98 -2186.95,2717.39 -2140.26,2670.7 RA505.5@-2140.26,2594.29
TX: J700.2 U700.17 | length 170.4
  Top Layer w10: U700.17@2408.12,-2486.65 2408.12,-2557.12 J700.2@2478.79,-2627.79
